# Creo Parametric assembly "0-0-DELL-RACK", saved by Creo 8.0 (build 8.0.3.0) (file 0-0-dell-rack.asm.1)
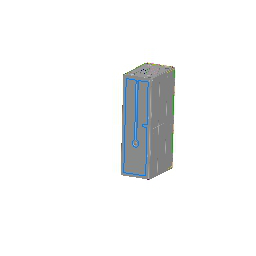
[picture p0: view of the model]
Units: millimeter Newton Second (mmNs); MM, TONNE, SECS

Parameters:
  MC_INTF = "01/14/2003 014"

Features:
  1. component "0-0-DELL-RACK_SKEL"
  2. datum plane "ASM_RIGHT"
  3. datum plane "ASM_TOP"
  4. datum plane "ASM_FRONT"
  5. coordinate system
  6. component "0-MAIN-FRAME"
  7. component "0-SIDE-PANEL"
  8. component "0-TOP-PANEL"
  9. component "0-FRONT-PANEL"
  10. component "0-REAR-PANEL"
  11. component "0-BOTTOM-PANEL"
  12. component
  13. component
  14. component
  15. component
  16. component
  17. component
  18. component
  19. component
  20. component
  21. component
  22. component
  23. component
  24. component
  25. component
  26. component
  27. component
  28. component
  29. component
  30. component
  31. component
  32. component
  33. component
  34. component
  35. component
  36. component
  37. component
  38. component "0-SIDE-PANEL"
  39. component
  40. component
  41. component
  42. component
  43. component
  44. component

Other named items: REP0001, REP0002, VIS0001, VIS0002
